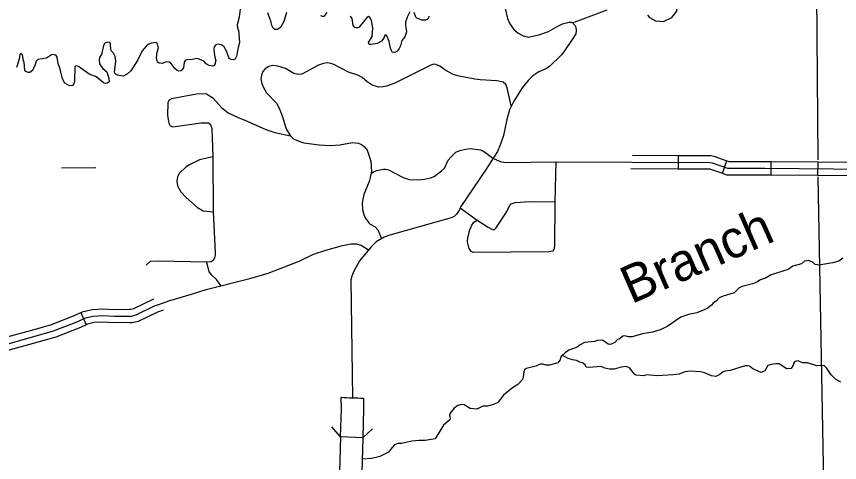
# Model space of a CAD drawing. Extents: x 1212896 to 1368412, y 378476 to 478763.
# Drawn here: x 1280046 to 1289328, y 408473 to 413498 of the extents above; entities that cross this region are included whole.
import ezdxf

# ---------------------------------------------------------------- set-up
doc = ezdxf.new("R2010")
doc.units = 0
for name, color, linetype in [('Level 10', 7, 'Continuous'), ('Level 31', 7, 'Continuous'), ('Level 32', 7, 'Continuous'), ('Level 35', 7, 'Continuous'), ('Level 37', 7, 'Continuous'), ('Level 45', 7, 'Continuous'), ('Level 5', 7, 'Continuous'), ('Level 9', 7, 'Continuous')]:
    doc.layers.add(name, color=color, linetype=linetype)

msp = doc.modelspace()

# ---------------------------------------------------------------- linework, layer by layer
at = {"layer": 'Level 10'}
msp.add_line((1283951.8, 408752.7), (1283702.1, 408764.2), dxfattribs=at)
for points in [[(1285556.8, 413589.4), (1285581.9, 413474.5), (1285609.4, 413416.6), (1285654.9, 413353), (1285679.1, 413331.2), (1285701.2, 413313.4), (1285760.5, 413280.8), (1285816.3, 413265.9), (1285938, 413292.5), (1286046.2, 413330.2), (1286150.7, 413390.2), (1286202.9, 413414), (1286279.5, 413435.9), (1286300.4, 413435.9), (1286317.5, 413428.3), (1286343.7, 413401.5), (1286353.9, 413379.6), (1286358.3, 413336.5), (1286352.7, 413304.4), (1286321.3, 413251), (1286228, 413110.9), (1286192.9, 413066.5), (1286057.2, 412936.5), (1286014.6, 412907), (1285937.1, 412873.1), (1285869.8, 412828.3), (1285817.4, 412777.6), (1285748.5, 412692.7), (1285653, 412542.4), (1285605.4, 412445.7), (1285574.5, 412339.1), (1285537.1, 412157.3), (1285505.6, 412060.8), (1285469.5, 411976.3), (1285333.9, 411765.5), (1285058.9, 411358.6)], [(1285058.9, 411358.6), (1285041.4, 411320.3), (1285008.9, 411272.9), (1284980.3, 411243.5), (1284947.5, 411229.2), (1284255.3, 411034.3), (1284193.7, 411011.6), (1284103.5, 410959.5), (1284049.1, 410906.9), (1283913.1, 410747.1), (1283852.5, 410629.2), (1283827.6, 410571.3), (1283815.8, 410529.4), (1283834.7, 409201.9)], [(1283702.1, 408764.2), (1283711.4, 409078.9), (1283709.6, 409209.5)], [(1283959.7, 409199.4), (1283961.5, 409076.9), (1283951.8, 408752.7)], [(1283702.1, 408764.2), (1283686.1, 408229.3)], [(1283951.8, 408752.7), (1283936.1, 408224.3)]]:
    msp.add_lwpolyline(points, dxfattribs=at)
msp.add_arc((1283958.2, 412250.4), 3051, 265.32598, 270.02912, dxfattribs=at)
at = {"layer": 'Level 31'}
for p, q in [((1280771.5, 410162), (1280833.2, 410025.3)), ((1280287.1, 409984.7), (1280287.1, 409984.7)), ((1280327.7, 409840.3), (1280327.7, 409840.3))]:
    msp.add_line(p, q, dxfattribs=at)
for points in [[(1285624.9, 412490), (1285579.9, 412695.9), (1285563.5, 412732.8), (1285533.4, 412757.5), (1285463.4, 412772.8), (1285275.7, 412783.8), (1285213.8, 412792.1), (1285039.9, 412826.3), (1284970.9, 412844.6), (1284878.6, 412897.8), (1284820.3, 412937.2), (1284775.2, 412957.8), (1284752.8, 412960.1), (1284718.8, 412949.5), (1284311.6, 412745.4), (1284219.1, 412712.2), (1284181.4, 412703.9), (1284130.5, 412700.3), (1284058.5, 412723.6), (1283999.2, 412763), (1283942.9, 412811.5), (1283897.6, 412836.5), (1283789.6, 412872), (1283626.2, 412956.4), (1283592.2, 412969.1), (1283551.2, 412974.7), (1283507.5, 412970.2), (1283451.7, 412948.5), (1283263.2, 412847.3), (1283223.1, 412844.3), (1283172.4, 412857.3), (1283081.1, 412910.5), (1282993.5, 412939.4), (1282938.1, 412945), (1282891.4, 412933.3), (1282851.7, 412908), (1282824.1, 412876.6), (1282809.5, 412838.4), (1282802, 412794.2), (1282814.5, 412742.3), (1282832.9, 412699.4), (1282867.4, 412638.6), (1282981.3, 412518.6), (1283018, 412444.9), (1283043.6, 412379), (1283083.9, 412243.2), (1283096.1, 412216.2), (1283137.7, 412152.6), (1283170.9, 412119.9), (1283210.1, 412099.2), (1283286.1, 412074), (1283460.9, 412051.8), (1283585.6, 412045.2), (1283693.7, 412051.6), (1283834.7, 412077.9), (1283903.6, 412072.6), (1283938.6, 412056), (1283966.8, 412035.2), (1284000.1, 411992.5), (1284042.3, 411868.7), (1284048.4, 411753.1), (1284036.2, 411683.3), (1284023.7, 411640.1)], [(1282187.5, 412625.9), (1282076.6, 412623.3), (1281792.9, 412569), (1281769.2, 412555.5), (1281753.4, 412528.4), (1281750.7, 412380.9), (1281763.1, 412295.4), (1281781, 412266.3), (1281809.1, 412253.5), (1282127.8, 412300), (1282177.6, 412300.5), (1282210.6, 412298.9), (1282235.7, 412280.9), (1282251.1, 412236.2), (1282262.3, 411918.7), (1282264.7, 411297.5), (1282286.3, 410839.8), (1282286.2, 410808.6), (1282280, 410780.6), (1282267.6, 410754.1), (1282242.9, 410734.9), (1282193.7, 410730.6), (1281644, 410742.7), (1281555.3, 410736.7), (1281508.8, 410697.1)], [(1284648.7, 411667), (1284714.6, 411678.9), (1284756.2, 411697), (1284840.4, 411758.1), (1284872, 411787.5), (1284915.9, 411879.1), (1284946.5, 411918.5), (1285001.8, 411971.2), (1285044.5, 411989.7), (1285111.2, 412004.5), (1285165, 412009.1), (1285276.8, 411995.5), (1285296.8, 411989.4), (1285352.1, 411955), (1285418.4, 411901.6)], [(1282262.3, 411918.7), (1282111.1, 411882), (1281995.9, 411827.6), (1281958.3, 411803.2), (1281881.2, 411729.2), (1281862.7, 411689.9), (1281855.2, 411643.8), (1281860.7, 411590.7), (1281900.3, 411524), (1281959.8, 411458.5), (1282086.6, 411347.7), (1282149.9, 411310.3), (1282264.7, 411297.5)], [(1284045.7, 411730.5), (1284081.4, 411751.9), (1284108.2, 411761.2), (1284183.9, 411776.3), (1284209.8, 411777.3), (1284241.8, 411770.7), (1284408.2, 411684.3), (1284473.3, 411662.9), (1284581.1, 411658.1), (1284648.7, 411667)], [(1284023.7, 411640.1), (1283962.4, 411492.1), (1283946.4, 411397.7), (1283950.1, 411323.6), (1283963.7, 411266.7), (1283980, 411230.8), (1284020.2, 411172.3), (1284034.6, 411159.2), (1284090.5, 411128.2), (1284120, 411095), (1284163.9, 410996.3)], [(1281651, 410253.8), (1281764.3, 410293.1), (1282020.9, 410368), (1282186.9, 410422.9), (1282677.4, 410544.4), (1282885.2, 410607.7), (1283232.9, 410742.8), (1283394.7, 410818.6), (1283533.9, 410864.2), (1283721.9, 410917.4), (1283820.4, 410935.5), (1283877.4, 410936.5), (1283933.3, 410921.6), (1284017.6, 410870.4)], [(1282352, 410465.7), (1282300.4, 410536.3), (1282249, 410584.9), (1282220.9, 410623.1), (1282193.7, 410730.6)], [(1281324.5, 410199.7), (1281330.6, 410199.8), (1281371.3, 410209.3), (1281597.1, 410317.8)], [(1280465.1, 409955.4), (1280739.3, 410063.6), (1280825.6, 410102.6), (1280910.3, 410121.9), (1281017.3, 410129.4), (1281154.6, 410120.2), (1281340.1, 410123.6), (1281396.8, 410136.8), (1281612.2, 410240.3), (1281651, 410253.8)], [(1280287.1, 409984.7), (1280440.7, 410027.9), (1280709.5, 410134), (1280771.5, 410162)], [(1280771.5, 410162), (1280801.2, 410175.4), (1280899, 410197.7), (1281017.2, 410206), (1281156.5, 410196.6), (1281324.5, 410199.7)], [(1281327.3, 410049.7), (1281349.2, 410050.1), (1281421.4, 410067), (1281640.3, 410172.2), (1281704, 410194.2)], [(1281327.3, 410049.7), (1281152.8, 410046.5), (1281017.4, 410055.6), (1280921.1, 410048.8), (1280849.2, 410032.5), (1280833.2, 410025.3)], [(1279763.4, 409824), (1279770.4, 409828.3), (1279901.5, 409876.3), (1280287.1, 409984.7)], [(1279925, 409803.6), (1280465.1, 409955.4)], [(1280833.2, 410025.3), (1280767.9, 409995.8), (1280488.6, 409885.6), (1280327.7, 409840.3)], [(1280327.7, 409840.3), (1279947.7, 409733.5), (1279835.4, 409692.3)]]:
    msp.add_lwpolyline(points, dxfattribs=at)
at = {"layer": 'Level 32'}
for p, q in [((1287511.9, 411782.3), (1287512.3, 411932.3)), ((1288006.8, 411732.3), (1288056.7, 411873.7)), ((1288556.6, 411715.4), (1288557.9, 411865.3)), ((1289084.5, 411710.5), (1289085.9, 411860.5))]:
    msp.add_line(p, q, dxfattribs=at)
for points in [[(1285418.4, 411901.6), (1285499.6, 411865.4), (1285559.5, 411855), (1286129, 411860.1), (1286984.1, 411857.5)], [(1286993, 411933.9), (1287512.3, 411932.3)], [(1287512.3, 411932.3), (1287876.3, 411931.2), (1287910.9, 411925.2), (1288056.7, 411873.7)], [(1286129, 411860.1), (1286117.7, 411411.1), (1286112.8, 410910), (1286106.2, 410873.9), (1286089.5, 410854.7), (1286054.6, 410848.3), (1285194.9, 410838), (1285172.3, 410851.3), (1285150.6, 410883.6), (1285132.8, 410958.6), (1285135.3, 411008.7), (1285159.4, 411094.2), (1285179.8, 411145.5), (1285205.4, 411180.8), (1285240, 411205.2)], [(1286984.1, 411857.5), (1287869.6, 411854.8), (1287891.6, 411851), (1288065.6, 411789.6), (1288486, 411789.6), (1290422.3, 411771.9)], [(1288056.7, 411873.7), (1288078.6, 411866), (1288486.4, 411866), (1288557.9, 411865.3)], [(1288557.9, 411865.3), (1289085.9, 411860.5)], [(1289085.9, 411860.5), (1289613.9, 411855.7)], [(1286973.6, 411783.9), (1287511.9, 411782.3)], [(1287511.9, 411782.3), (1287863.3, 411781.2), (1287873, 411779.5), (1288006.8, 411732.3)], [(1288006.8, 411732.3), (1288052.9, 411716), (1288485.7, 411716), (1288556.6, 411715.4)], [(1288556.6, 411715.4), (1289084.5, 411710.5)], [(1289084.5, 411710.5), (1289612.5, 411705.7)], [(1285050.1, 411342.5), (1285240, 411205.2), (1285366.5, 411124.4), (1285415.7, 411097.9), (1285435.6, 411098.1), (1285452.4, 411112.3), (1285571.3, 411292), (1285607.5, 411363.5), (1285626.2, 411385.8), (1285669.9, 411403.3), (1285835.4, 411414.1), (1286117.7, 411411.1)]]:
    msp.add_lwpolyline(points, dxfattribs=at)
at = {"layer": 'Level 35'}
for points in [[(1289320.4, 410741.1), (1289249.7, 410721.3), (1289096.4, 410695.6), (1289052.4, 410703.2), (1289031.2, 410728), (1288978.9, 410750.7), (1288931.4, 410740), (1288898.8, 410709.6), (1288802.3, 410683.5), (1288748.8, 410646.8), (1288557.9, 410586.6), (1288492.4, 410548.9), (1288435.8, 410530.2), (1288395.1, 410506.7), (1288344.5, 410485.1), (1288229.1, 410454.8), (1288195.3, 410440.5), (1288139, 410384.7), (1288013.7, 410348.3), (1287969.1, 410326.8), (1287938.5, 410293.4), (1287902.8, 410267), (1287883.1, 410245.7), (1287835.6, 410209.1), (1287802.9, 410191.7), (1287718.4, 410159.8), (1287624.9, 410140.7), (1287538.4, 410109.7), (1287383.8, 410006.9), (1287306.4, 409969), (1287216.9, 409942.9), (1287106.4, 409923.7), (1286990, 409890.4), (1286946.2, 409887.9), (1286908.2, 409900.5), (1286882.1, 409897.9), (1286841.8, 409864.1), (1286823.8, 409859.6), (1286795.2, 409825.2), (1286746.6, 409802.6), (1286719.6, 409805.3), (1286653.3, 409851.7), (1286599.5, 409846.1), (1286562.7, 409834.7), (1286453.1, 409825.5), (1286403.5, 409798.9), (1286370.8, 409773.5), (1286275.4, 409739.4), (1286233.8, 409709.9), (1286216.1, 409688.7), (1286201.2, 409682.5), (1286182.5, 409657.3), (1286175.8, 409630.1), (1286151.2, 409596.8), (1286058.7, 409570.8), (1286017.8, 409569.3), (1285978.8, 409580.9), (1285951.8, 409582.4), (1285902.2, 409557.1), (1285794.8, 409533.8), (1285777.9, 409524.6), (1285766.2, 409494.5), (1285760.8, 409439.3), (1285751.2, 409408.1), (1285699.9, 409353.5), (1285640.4, 409313.7), (1285538.5, 409233.5), (1285473.5, 409148.6), (1285423.9, 409127), (1285357.2, 409108.3), (1285305.4, 409106.7), (1285235.9, 409075.9), (1285161, 409081.1), (1285093.8, 409121.5), (1285062.3, 409127.6), (1285025, 409116.7), (1284982.4, 409085.2), (1284938.1, 409029.6), (1284930.7, 409006.4), (1284935.7, 408970.5), (1284932.9, 408955.4)], [(1289364.9, 410773.7), (1289320.4, 410741.1)], [(1288808.6, 409576.3), (1288780.2, 409530.9), (1288728.3, 409528.4), (1288646.9, 409584.6), (1288608, 409586.2), (1288556.2, 409578.6), (1288517.5, 409566.2), (1288484.2, 409504.7), (1288445.5, 409487.2), (1288349.3, 409530.3), (1288311.1, 409556.9), (1288285.1, 409563.7), (1288265.1, 409562.4), (1288093.1, 409511.5), (1288037.3, 409502.9), (1288008.5, 409492.5), (1287975.9, 409466.1), (1287931.2, 409442.6), (1287884.3, 409451.1), (1287806.1, 409483.4), (1287758.1, 409493.9), (1287641.4, 409500.6), (1287583.6, 409494), (1287518, 409468.2), (1287453.3, 409459.5), (1287268.8, 409450.5), (1287152, 409460.3), (1287117.3, 409448.9), (1287031.4, 409458), (1287015.3, 409469.8), (1286957.7, 409539.4), (1286919.7, 409554), (1286865.9, 409547.4), (1286786.3, 409526.5), (1286734.4, 409524.9), (1286679.5, 409534.4), (1286639.4, 409553), (1286503.9, 409542.5), (1286471.8, 409548.7), (1286460.7, 409572.1), (1286430.9, 409595.6), (1286398.5, 409602.5), (1286362.4, 409621.1), (1286317.5, 409628.7), (1286267.4, 409644.1), (1286201.2, 409682.5)], [(1289341.3, 409377.6), (1289283.1, 409413.1), (1289233.7, 409461.6), (1289179, 409541.2), (1289156.9, 409563), (1289143.8, 409567.9), (1289072.1, 409562.1), (1288965, 409595), (1288908.2, 409595.4), (1288861, 409619), (1288822.9, 409611.1), (1288807.3, 409589.8), (1288808.6, 409576.3)], [(1284932.9, 408955.4), (1284862.7, 408893.6), (1284769.5, 408741.2), (1284656.6, 408719.4), (1284586.2, 408720.2), (1284506.5, 408714.4), (1284390, 408687.1), (1284348.1, 408688.6), (1284307.4, 408673.1), (1284263, 408620.6), (1284243.4, 408588.3), (1284145.2, 408542.1), (1284048.6, 408520.1), (1283949.4, 408509.4)]]:
    msp.add_lwpolyline(points, dxfattribs=at)
at = {"layer": 'Level 37'}
for points in [[(1283702.1, 408764.2), (1283601, 408875)], [(1284062.6, 408853.7), (1283951.8, 408752.7)]]:
    msp.add_lwpolyline(points, dxfattribs=at)
at = {"layer": 'Level 45'}
for points in [[(1287162.7, 413513.1), (1287184.6, 413487.4), (1287253.7, 413448.7), (1287341.3, 413442.8), (1287435.4, 413486.3), (1287494.3, 413559.9), (1287520.9, 413790.3), (1287538.8, 413853.5)], [(1286317.5, 413428.3), (1286707.2, 413574.9)], [(1282187.5, 412625.9), (1282262.2, 412580.2), (1282359.4, 412473.8), (1282431.8, 412412.5), (1282552.3, 412354.7), (1282615.2, 412332.3), (1282857.6, 412226.7), (1282961.7, 412191.7), (1283137.7, 412152.6)]]:
    msp.add_lwpolyline(points, dxfattribs=at)
at = {"layer": 'Level 5'}
for points in [[(1289059, 414686.7), (1289081.5, 411882.1)], [(1280941.7, 411791.3), (1280553.2, 411789.6)], [(1289084, 411690), (1289181.1, 406415)]]:
    msp.add_lwpolyline(points, dxfattribs=at)
at = {"layer": 'Level 9'}
for points in [[(1282569.5, 413580.3), (1282557.4, 413492), (1282534.4, 413404.6), (1282539.4, 413369), (1282549, 413340.6), (1282560.3, 413209.5), (1282537.4, 413115), (1282527.1, 413048.8), (1282511, 413018.5), (1282489.6, 413008.3), (1282465.6, 413012.1), (1282446.5, 413024.9), (1282418.8, 413101.7), (1282400.5, 413134.6), (1282387.3, 413155.5), (1282357.2, 413177.2)], [(1283092.5, 413542.9), (1283059.7, 413442.3), (1283025.4, 413374.8), (1282990.7, 413353.4), (1282959.8, 413352.1), (1282939.4, 413367.8), (1282925.5, 413396.8), (1282915, 413447.8), (1282905.8, 413463.7), (1282882.5, 413539.2)], [(1283545.4, 413542.7), (1283513.9, 413498.3), (1283501, 413497.2), (1283478.9, 413505.9)], [(1284480.9, 413551.8), (1284450.6, 413489.3), (1284433.2, 413435.1), (1284431.6, 413401), (1284444.3, 413323.9), (1284425.9, 413269.6), (1284390.5, 413226.2), (1284375.1, 413165.9), (1284362.4, 413138.7), (1284340.8, 413106.4), (1284312.1, 413091.1), (1284284.1, 413094.8), (1284265.7, 413140.7), (1284247.9, 413216.6), (1284218.3, 413287.4), (1284199.3, 413287.2), (1284187.7, 413255.1), (1284161.1, 413221.7), (1284115.5, 413193.2), (1284044.8, 413181.4), (1284024.8, 413184.2), (1284015.6, 413205.1), (1284056.8, 413273.7), (1284064.8, 413370), (1284051, 413454), (1284031.7, 413486.8), (1284016.9, 413497.9), (1283999.7, 413491.5), (1283910.1, 413379.3), (1283893.3, 413369.1), (1283876.3, 413369.9), (1283862.3, 413373.8), (1283842.1, 413395.6), (1283830.3, 413476.7), (1283814.1, 413501.5)], [(1284696.9, 413502), (1284693.1, 413480.9), (1284677.3, 413463.7), (1284659.4, 413458.5), (1284616.5, 413458.1), (1284560.4, 413478.5), (1284550.3, 413492.4), (1284530.9, 413543.3)], [(1282357.2, 413177.2), (1282312.2, 413184.8), (1282289.4, 413175.5), (1282275.6, 413156.3), (1282270.9, 413126.2), (1282274.2, 413093.2), (1282283.8, 413038.2), (1282296.1, 413003.2), (1282279.7, 412945.9), (1282261.9, 412939.7), (1282219.9, 412945.3), (1282185.8, 412964), (1282157.5, 412996.7), (1282095.4, 413021.1), (1282076.8, 413024.6), (1282032.7, 413013.4), (1281962.9, 413009.7), (1281947, 413003.5), (1281936.6, 412982.7), (1281930.9, 412921.1), (1281903.2, 412887.3), (1281878.4, 412883.5), (1281858.4, 412889.3), (1281831.2, 412912.1), (1281785.5, 412973.7), (1281768.1, 412984), (1281739.4, 412985.9), (1281691, 412969.7), (1281658.9, 412973.8), (1281637, 412985.1), (1281625.5, 413033.1), (1281632.8, 413097.3), (1281646.3, 413146.5), (1281636.9, 413188.5), (1281621.8, 413204.4), (1281566.7, 413197.5), (1281532.2, 413182.4), (1281514.4, 413168.2), (1281465.1, 413110.5), (1281415.3, 413008.8), (1281336.8, 412887.7), (1281300.2, 412853.2), (1281248.6, 412824.6), (1281181.7, 412835.9), (1281159.6, 412850.7), (1281153.4, 412868.7), (1281165.1, 412996.1), (1281158.6, 413046.1), (1281139.2, 413084), (1281117.1, 413107.8), (1281111.9, 413122.7), (1281108.3, 413185.8), (1281098.1, 413203.8), (1281076.1, 413207.5), (1281044.3, 413196.2), (1281028.6, 413171.9), (1281005.7, 413070.5), (1280983.1, 413036.2), (1280977.4, 413010.1), (1280982.9, 412964), (1281021.3, 412913.4), (1281063.6, 412875.7), (1281087.3, 412798.8)], [(1281087.3, 412798.8), (1281093.6, 412763.8), (1281070.9, 412746.6), (1281053, 412744.3), (1281026.9, 412751.1), (1280957.5, 412810.5), (1280937.4, 412822.3), (1280864.4, 412846.5), (1280745.8, 412934.4), (1280722.9, 412944), (1280703.9, 412935), (1280702.6, 412765.6), (1280692.9, 412739.5), (1280678.1, 412722.3), (1280646.3, 412715.9), (1280591.1, 412746.4), (1280563.7, 412794.2), (1280539.6, 412904.2), (1280518, 412968.1), (1280505.3, 413040.1), (1280495.2, 413058), (1280469.1, 413069.7), (1280441.2, 413064.4), (1280383.7, 413029.7), (1280288.1, 413013.7), (1280270.4, 412996.5), (1280257.9, 412952.2), (1280227.6, 412887.8), (1280198.9, 412865.4), (1280177.9, 412866.2), (1280151.9, 412877.9), (1280142.7, 412894.9), (1280131.9, 412978.9), (1280121.6, 413011.9), (1280117.2, 413047.9), (1280113.1, 413064.9), (1280099.9, 413079.8), (1280083.1, 413072.6), (1280075.7, 413016.4), (1280045.7, 412922.9)]]:
    msp.add_lwpolyline(points, dxfattribs=at)

# ---------------------------------------------------------------- texts
at = {"layer": 'Level 35'}
msp.add_text('Branch', height=422.4, rotation=23.75741, dxfattribs=at).set_placement((1286980, 410255))

doc.saveas('drawing.dxf')
